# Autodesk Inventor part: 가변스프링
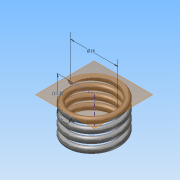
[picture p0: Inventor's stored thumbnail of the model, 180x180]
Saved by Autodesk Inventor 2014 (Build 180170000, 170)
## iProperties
Created: 2015-04
Part Number: 가변스프링
Material: 강철, 탄소
Document SubType Name: Modeling
Designer: Administrator
Density: 7.87 g/cm^3
Appearance: 반연마
Mass: 4.78768 g
Surface Area: 12.5241 cm^2
Volume: 0.608346 cm^3
Author: Administrator
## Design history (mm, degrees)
sketch "스케치1"
  geometry: L1 (0, 0)-(-8, 0); L2 (-8, 0)-(-8, 11.5); L3 (-8, 11.5)-(0, 11.5); L4 (0, 11.5)-(0, 0); C1 r 1 at (-8, 0)
  constraints: 8 end point, 2 parallel, 1 centre point, 1 coincident, 1 horizontal, 1 perpendicular
  dimensions: "d5" = 16 diameter of L2 L4; "d6" = 11.50049 distance between parallel lines of L1 L3 (derived); "d7" = 2 diameter of C1
feature "코일1" pitch "d8" = 10; turns "d10" = 4; dims "d9" = 11.50049 (= d6), "d11" = 0, angle "d12" = 90 deg, angle "d13" = 90 deg, "d14" = 0, "d15" = 0
sketch "스케치2"
  geometry: L1 (9, 0)-(7, 0) reference; 1 further point
  constraints: 1 horizontal alignment
extrude "돌출1" cut sketch "스케치2" stored distance "d16" = 10; taper "d17" = 0 deg
node "작업 평면1"
sketch "스케치3"
  geometry: L1 (7, 0)-(9, 0) reference; 1 further point
  constraints: 1 horizontal alignment
extrude "돌출2" cut sketch "스케치3" stored distance "d18" = 10; taper "d19" = 0 deg
node "솔리드1"
node "절단 모서리 투영1"
node "절단 모서리 투영2"
